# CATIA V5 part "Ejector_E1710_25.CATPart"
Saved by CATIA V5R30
Part number: Vyhazovac_7x160_2
Nomenclature: E1710/7x160
Description: MEUSBURGER
Property "Material": "1.221"
Publications: "__DrillHole", "Base"
Bounding box of the stored display mesh (mm): x -5.992 to 5.992, y -5.992 to 5.992, z 0 to 156.5
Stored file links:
  E:\Bakalarka\Model\Forma_v7\Ejector_E1710_25.CATPart
  E:\dev\MoldDesign\intel_a\startup\components\MoldCatalog\Ejector\Meusburger\Ejector_E1710\TableE1710.txt
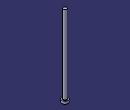
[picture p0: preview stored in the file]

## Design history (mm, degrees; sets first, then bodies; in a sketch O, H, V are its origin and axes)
Parameters
  Ref = "E1710/7x160" {design table}
  D1 = 7 mm {design table}
  D3 = 12 mm {design table}
  L = 160 mm {design table}
  L3 = 5 mm {design table}
  R = 0.5 mm {design table}
  k_d3 = 13 mm {design table}
  k_d1 = 7.2 mm {design table}
  k_F = 0.5 mm {design table}
  kl = 17 mm {design table}
  Mat = "1.221" {design table}
  HeatTreat = "ISO6751" {design table}
  Offset_Parting = 10 mm
  Anti_Rotation = "Normal"
  Anti_Rotation_D = 4 mm
  Anti_Rotation_D_Icut = 4 mm
  Add_Length_L = 1.3377 mm
  Add_Length_D3 = 0 mm
  SupplierRef = "Meusburger 2017"
  BmpRef = "F_MldEjectorD1"
  DrillHole_Length = 225 mm
  ValidationTest = false
  Anti_Rotation_D_min = 4 mm {= OffSet_D1 /2}
  Anti_Rotation_D_max = 5.925 mm {= D3/2-0.075mm}
  Anti_Rotation_D_ref = 4 mm {= Anti_Rotation_D}
  Anti_Rotation_D_Icut_ref = 4 mm {= Anti_Rotation_D_Icut}
  Anti_Rotation_Ref_Icut = 2.3246 mm
  Offset_L = 20 mm
  D = 7 mm {= D1}
  OffSet_D1 = 8 mm {= D1+2*R}
  OffSet_D3 = 13 mm {= D3+1mm}
  XG_Split = -80 mm
  YG_Split = 25 mm
  ZG_Split = -198 mm
  DirX_Split = 0 mm
  DirY_Split = 0 mm
  DirZ_Split = 1 mm
Set1 "BaseBody"
  Point1 "Base": (0, 0, 0)
  Plane1: type Offset, RefPlane xy-plane, Offset 225 {= DrillHole_Length}, reversed
  Sketch1 "Sketch.2" on xy-plane, origin (0, 0, 0), H (1, 0, 0), V (0, 1, 0)
    point P1 (-0.46, 1.1623)
    point P2 (0.46, 1.1623)
    construction line L1 (-0.46, 1.1623) -> (0.46, 1.1623)
    point P3 (0.46, -1.1623)
    line L2 (0.46, -1.1623) -> (0.46, 1.1623)
    point P4 (-0.46, -1.1623)
    construction line L3 (0.46, -1.1623) -> (-0.46, -1.1623)
    line L4 (-0.46, 1.1623) -> (-0.46, -1.1623)
    point P5 (-0.21, 1.1623)
    arc A1 centre (-0.21, 1.1623) radius 0.25 from (-0.21, 1.4123) to (-0.46, 1.1623) ccw
    point P7 (0.21, 1.1623)
    point P8 (0.21, 1.4123)
    arc A2 centre (0.21, 1.1623) radius 0.25 from (0.46, 1.1623) to (0.21, 1.4123) ccw
    line L5 (-0.21, 1.4123) -> (0.21, 1.4123)
    point P9 (-0.46, -1.1623)
    arc A3 centre (-0.21, -1.1623) radius 0.25 from (-0.46, -1.1623) to (-0.21, -1.4123) ccw
    point P11 (0.21, -1.4123)
    line L6 (-0.21, -1.4123) -> (0.21, -1.4123)
    point P12 (0.46, -1.1623)
    arc A4 centre (0.21, -1.1623) radius 0.25 from (0.21, -1.4123) to (0.46, -1.1623) ccw
    point P14 (-0.46, 1.1623)
    point P15 (-0.46, -1.1623)
    point P16 (0.46, 1.1623)
    point P17 (0.46, -1.1623)
    reference projected circle E1 centre (0, 0) radius 1.25 from edge [face of Shaft1 from Sketch2.L3 | face of Shaft1 from Sketch2.L4]
    reference projected circle E2 centre (0, 0) radius 1.25 from edge [face of Shaft1 from Sketch2.L3 | face of Shaft1 from Sketch2.L4]
    reference projected circle E3 centre (0, 0) radius 1.25 from edge [face of Shaft1 from Sketch2.L3 | face of Shaft1 from Sketch2.L4]
    reference projected circle E4 centre (0, 0) radius 1.25 from edge [face of Shaft1 from Sketch2.L3 | face of Shaft1 from Sketch2.L4]
    point P18 (-0.46, -1.1623)
    point P19 (-0.21, -1.4123)
    point P20 (0.21, -1.4123)
    point P21 (0.46, -1.1623)
    point P22 (-0.21, -1.4123)
    point P23 (0.21, -1.4123)
    distance P14 P15 = 2.3246 (reference)
    distance P16 P17 = 2.3246 (reference)
    distance L1 P14 = 0 (reference)
    radius A1 = 3.5
    distance L4 V = 4.01
    distance L2 V = 5.935
    distance L5 L6 = 12
    horizontal: L1 H, L3 H, L5 H
    vertical: L2 V, L4 V
    coincidence: P5 L1, P7 L1, P3 P12, P14 L4, P15 L4, P16 L2, P17 L2, P14 E1, P15 E2, P16 E3, P17 E4, P3 P21, P4 P18, P20 P23, P19 P22
    tangency: A1 L4, A2 L2, A2 L5, A1 L5
    symmetry: P1 P9 H, A1 A3 H, P8 P11 H, L5 L6 H, P2 P12 H, A2 A4 H
  DatumSurface1
Body1 "PartBody" (main body)
  Sketch2 "Sketch.1" on zx-plane, origin (0, 0, 0), H (-1, 0, 0), V (0, 0, 1)
    point P1 (0, 160)
    line L1 (3.5, 160) -> (0, 160)
    line L2 (3.5, 5) -> (3.5, 160)
    line L3 (6, 5) -> (3.5, 5)
    line L4 (6, 0) -> (6, 5)
    point P5 (0, 0)
    line L5 (0, 0) -> (6, 0)
    point P6 (0, 160)
    axis line L6 (0, 160) -> (0, 0)
    point P7 (0, 0)
    point P8 (3.5, 5)
    point P9 (3.5, 5)
    line L7 (0, 160) -> (0, 0)
    distance L5 L3 = 5 {= L3}
    distance L5 L1 = 160 {= L}
    distance L2 L6 = 3.5 {= D1 /2}
    distance L4 L6 = 6 {= D3 /2}
    coincidence: L6 P5, P1 L6, L5 H, L6 V, P7 O, P6 P1, P8 P9
    vertical: L2 V, L7 V
    horizontal: L1 H
  Shaft1 "Shaft.1": profile Sketch2, axis Sketch2.L6, angle 360
  Pocket1 "Pocket.1": profile Sketch1, direction (0, 0, 1), length 6, outer side, deactivated
  Pocket2 "Pocket.2": profile Sketch1, direction (0, 0, 1), length 6, outer side, deactivated
  Fillet1: radius 0.5 {= R}, on edge [face of Shaft1 from Sketch2.L2 | face of Shaft1 from Sketch2.L3]
  Pocket3: profile face of Shaft1 from Sketch2.L1, direction along face of DatumSurface1, up to face of DatumSurface1
Body2 "__DrillHole"
  Sketch3 "Sketch.3" on face of Shaft1, origin (0, 0, 0), H (1, 0, 0), V (0, -1, 0)
    point P1 (0, 0)
    reference projected point E1 (0, 0) from Point1
    coincidence: E1 P1
  Hole1 "Hole.1": placed by Sketch3, at (0, 0, 0) direction (0, 0, 1), diameter 8 {= OffSet_D1}, depth 140 {= L-Offset_L}
  Sketch4 "Sketch.4" on face of Shaft1, origin (0, 0, 0), H (1, 0, 0), V (0, -1, 0)
    point P1 (0, 0)
    reference projected point E1 (0, 0) from Point1
    coincidence: E1 P1
  Hole2 "Hole.2": placed by Sketch4, at (0, 0, 0) direction (0, 0, 1), diameter 7 {= D1}, depth 160 {= L}
  Sketch5 "Sketch.5" on face of Shaft1 from Sketch2.L3, origin (0, 0, 5), H (1, 0, 0), V (0, 1, 0)
    point P1 (0, 0)
    reference projected point E1 (0, 0) from Point1
    coincidence: E1 P1
  Hole3 "Hole.3": placed by Sketch5, at (0, 0, 5) direction (0, 0, -1), diameter 13 {= OffSet_D3}, depth 230 {= L3 +DrillHole_Length}
  Chamfer1: length 0.5 {= k_F}, angle 45, on edge [face of Hole1 | face of Hole3]
  Body3 "__Body.1"
    Pocket4 "Pocket.3": profile Sketch1, direction (0, 0, -1), length 225, opposite side length 5, deactivated
  Assemble1: tool Body3
  Chamfer2: length 0.5 {= k_F}, angle 45, on edge [start face of Pocket4 | face of Hole1], deactivated
  Body4 "__Body.2"
    Pocket5 "Pocket.4": profile Sketch1, direction (0, 0, -1), length 225, opposite side length 5, deactivated
  Assemble2: tool Body4
  Chamfer3: length 0.5 {= k_F}, angle 45, on edge [start face of Pocket5 | face of Hole1], deactivated
Relations
  design table "TableE1710", configuration 278, drives Ref, D1, D3, L, L3, R, k_d3, k_d1, k_F, kl, Mat, HeatTreat
  Offset_L = 20mm (deactivated)
  rule "Cut_Head_rule":
    let sketch_cut (length)
    let PartBody_Pocket_Sketch (Boolean)
    let I_PartBody_Pocket (Boolean)
    let D_PartBody_Pocket (Boolean)
    let N_DrillHole_Hole (Boolean)
    let N_DrillHole_Hole_Sketch (Boolean)
    let I_DrillHole_Pocket (Boolean)
    let D_DrillHole_Pocket (Boolean)
    /* --------------------------------------------------------------------------------------*/
    if Anti_Rotation =="Normal"
    {
    	sketch_cut=Anti_Rotation_D_max
    	PartBody_Pocket_Sketch = false
    	I_PartBody_Pocket = false
    	D_PartBody_Pocket = false
    	N_DrillHole_Hole = true
    	N_DrillHole_Hole_Sketch = true
    	I_DrillHole_Pocket = false
    	D_DrillHole_Pocket = false
    	Chamfer1.Activity= true
    	Chamfer2.Activity= false
    	Chamfer3.Activity= false
    }
    if Anti_Rotation == "I_Cut"
    {
    	sketch_cut=Anti_Rotation_D_Icut_ref
    	PartBody_Pocket_Sketch = true
    	I_PartBody_Pocket = true
    	D_PartBody_Pocket = false
    	N_DrillHole_Hole = false
    	N_DrillHole_Hole_Sketch = false
    	I_DrillHole_Pocket = true
    	D_DrillHole_Pocket = false
    	Chamfer1.Activity= false
    	Chamfer2.Activity= true
    	Chamfer3.Activity= false
    }
    if Anti_Rotation =="D_Cut"
    {
    	sketch_cut=Anti_Rotation_D_max
    	PartBody_Pocket_Sketch = true
    	I_PartBody_Pocket = false
    	D_PartBody_Pocket = true
    	N_DrillHole_Hole = false
    	N_DrillHole_Hole_Sketch = false
    	I_DrillHole_Pocket = false
    	D_DrillHole_Pocket = true
    	Chamfer1.Activity= false
    	Chamfer2.Activity= false
    	Chamfer3.Activity= true
    }
    /* --------------------------------------------------------------------------------------*/
    Sketch1.distance(L2 V) = sketch_cut+0.01mm
    Sketch1.distance(L4 V) =Anti_Rotation_D_ref+0.01mm
    Sketch1.radius(A1) =D/2
    Pocket4.FirstLimit.Depth = DrillHole_Length
    Pocket5.FirstLimit.Depth = DrillHole_Length
    Pocket1.FirstLimit.Depth = L3+1mm
    Pocket2.FirstLimit.Depth = L3+1mm
    Pocket4.SecondLimit.Depth = L3
    Pocket5.SecondLimit.Depth =L3
    Pocket1.Activity = I_PartBody_Pocket
    Pocket2.Activity = D_PartBody_Pocket
    Sketch1.Activity =PartBody_Pocket_Sketch
    Hole3.Activity= N_DrillHole_Hole
    Sketch5.Activity = N_DrillHole_Hole_Sketch
    Pocket4.Activity = I_DrillHole_Pocket
    Pocket5.Activity  = D_DrillHole_Pocket
  rule "Anti_Rotation_Icut_constrain":
    let Ref1(length)
    let Ref2(length)
    let Ref3(length)
    let Diam1(length)
    let Diam2(length)
    let Add_Length_Lmin (length)
    Ref1=Sketch1.distance(P14 P15)
    Ref2=Sketch1.distance(P16 P17)
    Diam1=D
    Diam2=D3
    /* --------------------------------------------------------------------*/
    if Ref1 >Ref2
    	Anti_Rotation_Ref_Icut = Ref1
    else
    	Anti_Rotation_Ref_Icut  =Ref2
    Add_Length_D3 .InferiorRange=Anti_Rotation_Ref_Icut /2+Diam1/2 -Diam2/2
    if Add_Length_D3 .InferiorRange<0mm
    	Add_Length_D3 .InferiorRange=0mm
    if ValidationTest == "true"
    	Ref3   = 2*Add_Length_L +Anti_Rotation_Ref_Icut  +2*Diam1/2
    else
    	Ref3  =Diam2+2*Add_Length_D3
    if Ref3 <Diam2
    {
    	Ref3 =Diam2
    }
    /* --------------------------------------------------------------------*/
    Sketch1.distance(L5 L6) = Ref3
    Add_Length_L .InferiorRange=Diam2/2-Anti_Rotation_Ref_Icut/2-Diam1/2
    Add_Length_Lmin=Diam2/2-Anti_Rotation_Ref_Icut/2-Diam1/2
    if Add_Length_Lmin<0mm
    	Add_Length_L .InferiorRange=0mm
    else
    	Add_Length_L .InferiorRange=Add_Length_Lmin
